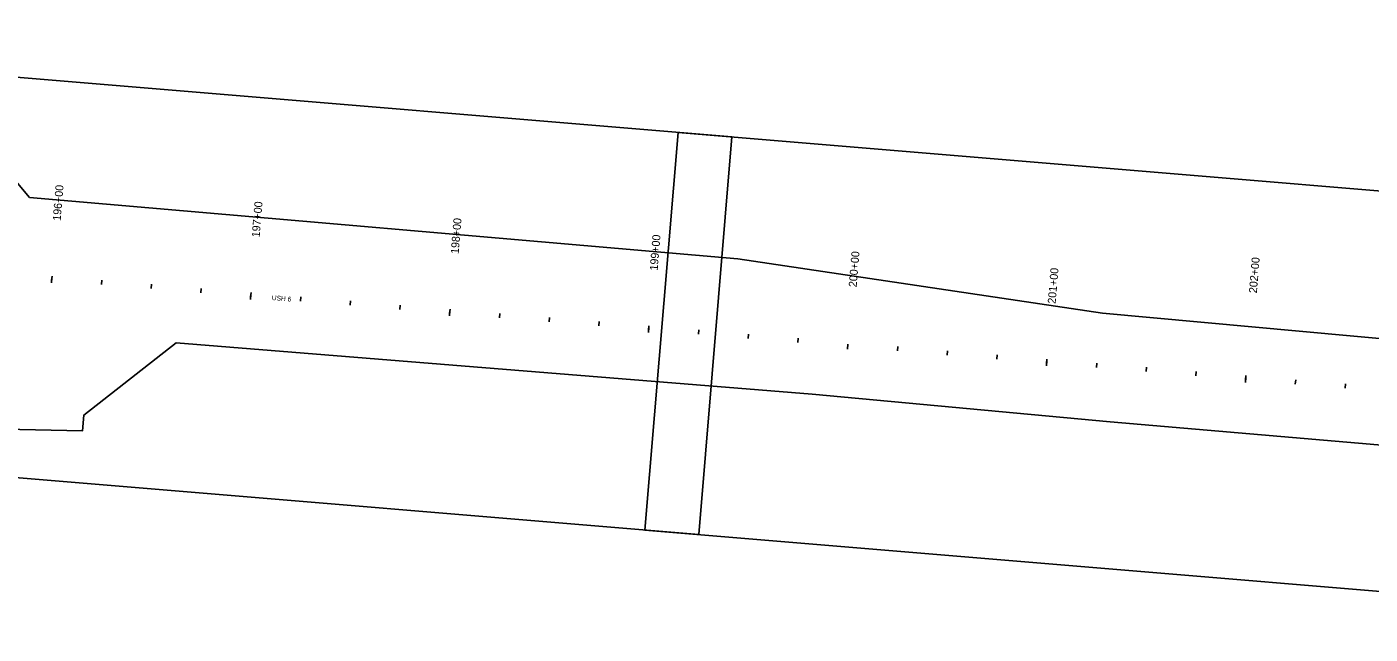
# Model space of a CAD drawing. Extents: x 20499876 to 20505320, y 7953544 to 7954108.
# Drawn here: x 20503290 to 20503963, y 7953584 to 7953888 of the extents above; entities that cross this region are included whole.
import ezdxf

# ---------------------------------------------------------------- set-up
doc = ezdxf.new("R2010")
doc.units = 0
for name, color, linetype in [('Alignment', 7, 'Continuous'), ('Curb', 7, 'Continuous'), ('Draft_0', 7, 'Continuous'), ('Draft_7', 7, 'Continuous'), ('UtilitiesBelowGround', 7, 'Continuous')]:
    doc.layers.add(name, color=color, linetype=linetype)

msp = doc.modelspace()

# ---------------------------------------------------------------- linework, layer by layer
at = {"layer": 'Alignment'}
for points in [[(20503018.63, 7953885.52), (20503002, 7953686.21), (20503626.83, 7953634.07), (20503643.46, 7953833.37)], [(20503616.55, 7953835.62), (20503599.92, 7953636.31), (20504224.75, 7953584.17), (20504241.38, 7953783.48)]]:
    msp.add_lwpolyline(points, close=True, dxfattribs=at)
at = {"layer": 'Curb'}
for p, q in [((20503302.8, 7953761.46), (20503302.98, 7953763.63)), ((20503402.45, 7953753.14), (20503402.63, 7953755.32)), ((20503502.11, 7953744.82), (20503502.29, 7953747)), ((20503601.76, 7953736.51), (20503601.94, 7953738.68)), ((20503701.51, 7953729.41), (20503701.31, 7953726.97)), ((20503801.07, 7953719.87), (20503801.25, 7953722.05)), ((20503900.72, 7953711.56), (20503900.9, 7953713.73))]:
    msp.add_line(p, q, dxfattribs=at)
at = {"layer": 'Draft_7'}
for p, q in [((20503302.9, 7953762.68), (20503302.7, 7953760.24)), ((20503327.71, 7953759.38), (20503327.89, 7953761.55)), ((20503352.63, 7953757.3), (20503352.81, 7953759.47)), ((20503377.54, 7953755.22), (20503377.72, 7953757.39)), ((20503402.55, 7953754.36), (20503402.35, 7953751.92)), ((20503427.37, 7953751.06), (20503427.55, 7953753.24)), ((20503452.28, 7953748.98), (20503452.46, 7953751.16)), ((20503477.19, 7953746.9), (20503477.37, 7953749.08)), ((20503502.21, 7953746.04), (20503502, 7953743.6)), ((20503527.02, 7953742.74), (20503527.2, 7953744.92)), ((20503551.93, 7953740.66), (20503552.11, 7953742.84)), ((20503576.85, 7953738.59), (20503577.03, 7953740.76)), ((20503601.86, 7953737.73), (20503601.66, 7953735.29)), ((20503626.67, 7953734.43), (20503626.85, 7953736.6)), ((20503651.59, 7953732.35), (20503651.77, 7953734.52)), ((20503676.5, 7953730.27), (20503676.68, 7953732.45)), ((20503701.51, 7953729.41), (20503701.31, 7953726.97)), ((20503726.33, 7953726.11), (20503726.51, 7953728.29)), ((20503751.24, 7953724.03), (20503751.42, 7953726.21)), ((20503776.15, 7953721.95), (20503776.33, 7953724.13)), ((20503801.17, 7953721.09), (20503800.96, 7953718.65)), ((20503825.98, 7953717.79), (20503826.16, 7953719.97)), ((20503850.89, 7953715.72), (20503851.08, 7953717.89)), ((20503875.81, 7953713.64), (20503875.99, 7953715.81)), ((20503900.82, 7953712.78), (20503900.62, 7953710.34)), ((20503925.63, 7953709.48), (20503925.82, 7953711.65)), ((20503950.55, 7953707.4), (20503950.73, 7953709.58))]:
    msp.add_line(p, q, dxfattribs=at)
at = {"layer": 'UtilitiesBelowGround'}
for points in [[(20502579.49, 7953887.98), (20502593.01, 7953888.5), (20502597.99, 7953888.06), (20502663.24, 7953867.31), (20502743.17, 7953845.01), (20502960.26, 7953827.03), (20503149.04, 7953802.5), (20503172.51, 7953801.74), (20503181.34, 7953817.32), (20503201.28, 7953847.18), (20503257.87, 7953843.36), (20503291.71, 7953802.91), (20503646.48, 7953772.26), (20503829.09, 7953744.97), (20504079.02, 7953722.08)], [(20503994.1, 7953676.75), (20503832.88, 7953690.55), (20503683.62, 7953704.36), (20503365.12, 7953730.13), (20503318.98, 7953693.96), (20503318.32, 7953686.11), (20503255.28, 7953687.43), (20503201.41, 7953693.27), (20503166.1, 7953705.05), (20503168.96, 7953719.94), (20503119.74, 7953739.09), (20502805.68, 7953763.59), (20502567.99, 7953764)]]:
    msp.add_lwpolyline(points, dxfattribs=at)

# ---------------------------------------------------------------- texts
at = {"layer": 'Curb'}
msp.add_text('200+00', height=4.008, rotation=85.22957, dxfattribs=at).set_placement((20503705.91, 7953757.92))
at = {"layer": 'Draft_0'}
msp.add_text('USH 6', height=2.4, rotation=355, dxfattribs=at).set_placement((20503412.96, 7953751.65))
at = {"layer": 'Draft_7'}
for s, p in [('196+00', (20503307.29, 7953791.18)), ('197+00', (20503406.94, 7953782.87)), ('198+00', (20503506.6, 7953774.55)), ('199+00', (20503606.25, 7953766.24)), ('200+00', (20503705.91, 7953757.92)), ('202+00', (20503906.34, 7953754.92)), ('201+00', (20503805.56, 7953749.6))]:
    msp.add_text(s, height=4.008, rotation=85.22957, dxfattribs=at).set_placement(p)

doc.saveas('drawing.dxf')
